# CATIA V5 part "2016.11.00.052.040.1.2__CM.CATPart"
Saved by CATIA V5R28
Part number: 2016.11.00.052.040.1.2__CM
Property "id_number": "2016.11.00.052.040.1.2"
Publications: "Absolute Axis System", "driver", "slider", "base", "cam diagram"
Bounding box of the stored display mesh (mm): x -40 to 135, y -49 to 49, z 0 to 180
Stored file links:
  N:\B2\Normteile\K\2016\11-14\005\cm\2016.11.00.052.040.1.2__CM.CATPart
  H:\CAD_Startmodelle\Tests\fill-in_PRT-SL_TEMPLATE.xlsx
  H:\CAD_Startmodelle\V5-R24\R24_TEMPLATE_PRT_FIBRO_CAM_TECNOLOGIES_INDEX.xlsx
  H:\z_Einordnen\170511__Anfrage_TK_HN\170511__CC01_TKHN.CATPart
  N:\B2\Normteile\K\2016\9xxx\2016.9024.1705.001\Entwurf_\170511__CC01_TKHN.CATPart
  N:\B2\Normteile\K\2016\9xxx\2016.9024.1707.006\Konstruktion\2016.9024.1707.006__HP__CUSTOMIZED_CAM_CM.CATPart
  N:\B2\Normteile\K\2016\9xxx\2016.9024.1707.005\Konstruktion\2016.9024.1707.005__HP__CUSTOMIZED_CAM_CM.CATPart
  N:\B2\Normteile\K\2016\9xxx\2016.9024.1707.008\Konstruktion\2016.9024.1707.008__HP__CUSTOMIZED_CAM_CM.CATPart
  N:\B2\Normteile\K\2016\9xxx\2016.9024.1707.009\Konstruktion\2016.9024.1707.009__HP__CUSTOMIZED_CAM_CM.CATPart
  N:\B2\Normteile\K\2016\9xxx\2016.9024.1707.010\Konstruktion\2016.9024.1707.010__HP__CUSTOMIZED_CAM_CM.CATPart
  N:\B2\Normteile\K\2016\9xxx\2016.9024.1708.002\Konstruktion\2016.9024.1708.002__HP__CUSTOMIZED_CAM_CM.CATPart
  N:\B2\Normteile\K\2016\9xxx\2016.9024.1802.001\Konstruktion\2016.9024.1802.001__HP__CUSTOMIZED_CAM_CM.CATPart
  N:\B2\Normteile\K\2016\9xxx\2016.9024.1802.002\Konstruktion\2016.9024.1802.002__HP__CUSTOMIZED_CAM_CM.CATPart
  N:\B2\Normteile\K\2016\9xxx\2016.9024.1811.003\Konstruktion\2016.9024.1811.003__HP__CUSTOMIZED_CAM_CM.CATPart
  N:\B2\Normteile\K\2016\9xxx\2016.9015.1811.001\Konstruktion\am\2016.9015.1811.001__AM__FCC_HV_DMC_0125-00.CATPart
  N:\B2\Normteile\K\2016\9xxx\2016.9024.1811.009\Konstruktion\2016.9024.1811.009__HP__CUSTOMIZED_CAM_CM.CATPart
  N:\B2\Normteile\K\2016\9xxx\2016.9024.1911.002\Konstruktion\am\2016.9024.1911.002__AM__CUSTOMIZED_CAM_CM.CATPart
  N:\B2\Normteile\K\2016\9xxx\2016.9024.2002.006\Konstruktion\2016.9024.2002.006__AM.CATPart
  N:\B2\Normteile\K\2016\9xxx\2016.9024.2004.001\Konstruktion\2016.9024.2004.001__AM__FCC_HV_CAEC_0260-45.CATPart
  N:\B2\Normteile\K\2016\9xxx\2016.9024.2006.002\Konstruktion\2016.9024.2006.002__AM__FCC_HV_CAEC_0260-40.CATPart
  N:\B2\Normteile\K\2016\9xxx\2016.9024.2006.005\Konstruktion\am\2016.9024.2006.005__AM__CFCC_HV_AEPC_0080-65.CATPart
  N:\B2\Normteile\K\2016\9xxx\2016.9024.2006.004\Konstruktion\am\2016.9024.2006.004__AM__CFCC_HV_AEC_0210-35.CATPart
  N:\B2\Normteile\K\2016\9xxx\2016.9026.2006.001\Konstruktion\am\2016.9026.2006.001__AM__FCC_LV_CAEC_0180-40.CATPart
  N:\B2\Normteile\K\2016\9xxx\2016.9015.2007.001\Konstruktion\am\2016.9015.2007.001__AM__FCC_HV_CDMPC_0090-00.CATPart
  N:\B2\Normteile\K\2016\9xxx\2016.9024.2005.001\Konstruktion\am\2016.9024.2005.001__AM__CFCC_HV_AEPC_1400-70.CATPart
  N:\B2\Normteile\K\2016\9xxx\2016.9024.2007.004\Konstruktion\am\2016.9024.2007.004__AM__CFCC_HV_AEC_1250-80.CATPart
  N:\B2\Normteile\K\2016\11-14\005\2016.11.00.052.040.1.02__AS__DIE_MOUNT_CAM__W52_A0_S40.CATProduct
  N:\B2\Normteile\K\2016\11-14\005\cm\2016.11.00.052.025.1.2__CM.CATPart
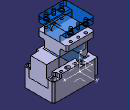
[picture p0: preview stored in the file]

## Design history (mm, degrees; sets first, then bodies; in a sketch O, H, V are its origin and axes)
Parameters
  group "process_parameters"
    modeltype = ""
    stocklist = ""
    id_number = "2016.11.00.052.040.1.2"
    id_number_rough_part = ""
    revision_index = ""
    revision_date = ""
    revision_description = ""
    category = ""
    material = ""
    manufacturing_information = ""
    standard = ""
  group "release_parameters_startmodel"
    sm_revision_index = "2016_00" {design table}
    sm_revision_date = "20.08.2016" {design table}
    sm_revision_name = "Meyer" {design table}
    sm_revision_description = "new part template FIBRO cam tecnologies" {design table}
AxisSystem1: origin (0, 0, 0), X (1, 0, 0), Y (0, 1, 0), Z (0, 0, 1)
Set1 "reference elements"
  Sketch1 "cam diagram" on ZX plane of AxisSystem1, origin (0, 0, 0), H (-1, 0, 0), V (0, 0, 1)
    line L1 (0, 0) -> (40, 0)
    line L2 (40, 0) -> (0, 40)
    point P2 (0, 40)
    line L3 (0, 40) -> (0, 0)
    length L1 = 40
    angle H L2 = 45
    horizontal: L1 H
    coincidence: P2 V
    vertical: L3 V
Body1 "finished_part" (main body)
  Body2 "rough_part"
  Add1 "rough_part": tool Body2
  Body3 "milling operations"
  Remove1 "milling operations": tool Body3
  Body4 "drilling operations"
  Remove2 "drilling operations": tool Body4
Body5 "driver"
  Solid1: solid without history
Body6 "slider"
  Solid2: solid without history
Body7 "base"
  Solid3: solid without history
Body8 "opened position"
  Body9 "slider"
    Body10 "slider"
      Solid4: linked copy from another document
    Assemble1: tool Body10
    Translate1: FirstPoint vertex [element of Sketch1 | element of Sketch1], SecondPoint vertex [element of Sketch1 | element of Sketch1], ToTransfor Assemble1
  Assemble2: tool Body9
  Body11 "driver"
    Body12 "driver"
      Solid5: linked copy from another document
    Assemble3: tool Body12
    Translate2: FirstPoint vertex [element of Sketch1 | element of Sketch1], SecondPoint vertex [element of Sketch1 | element of Sketch1], ToTransfor Assemble3
  Assemble4: tool Body11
